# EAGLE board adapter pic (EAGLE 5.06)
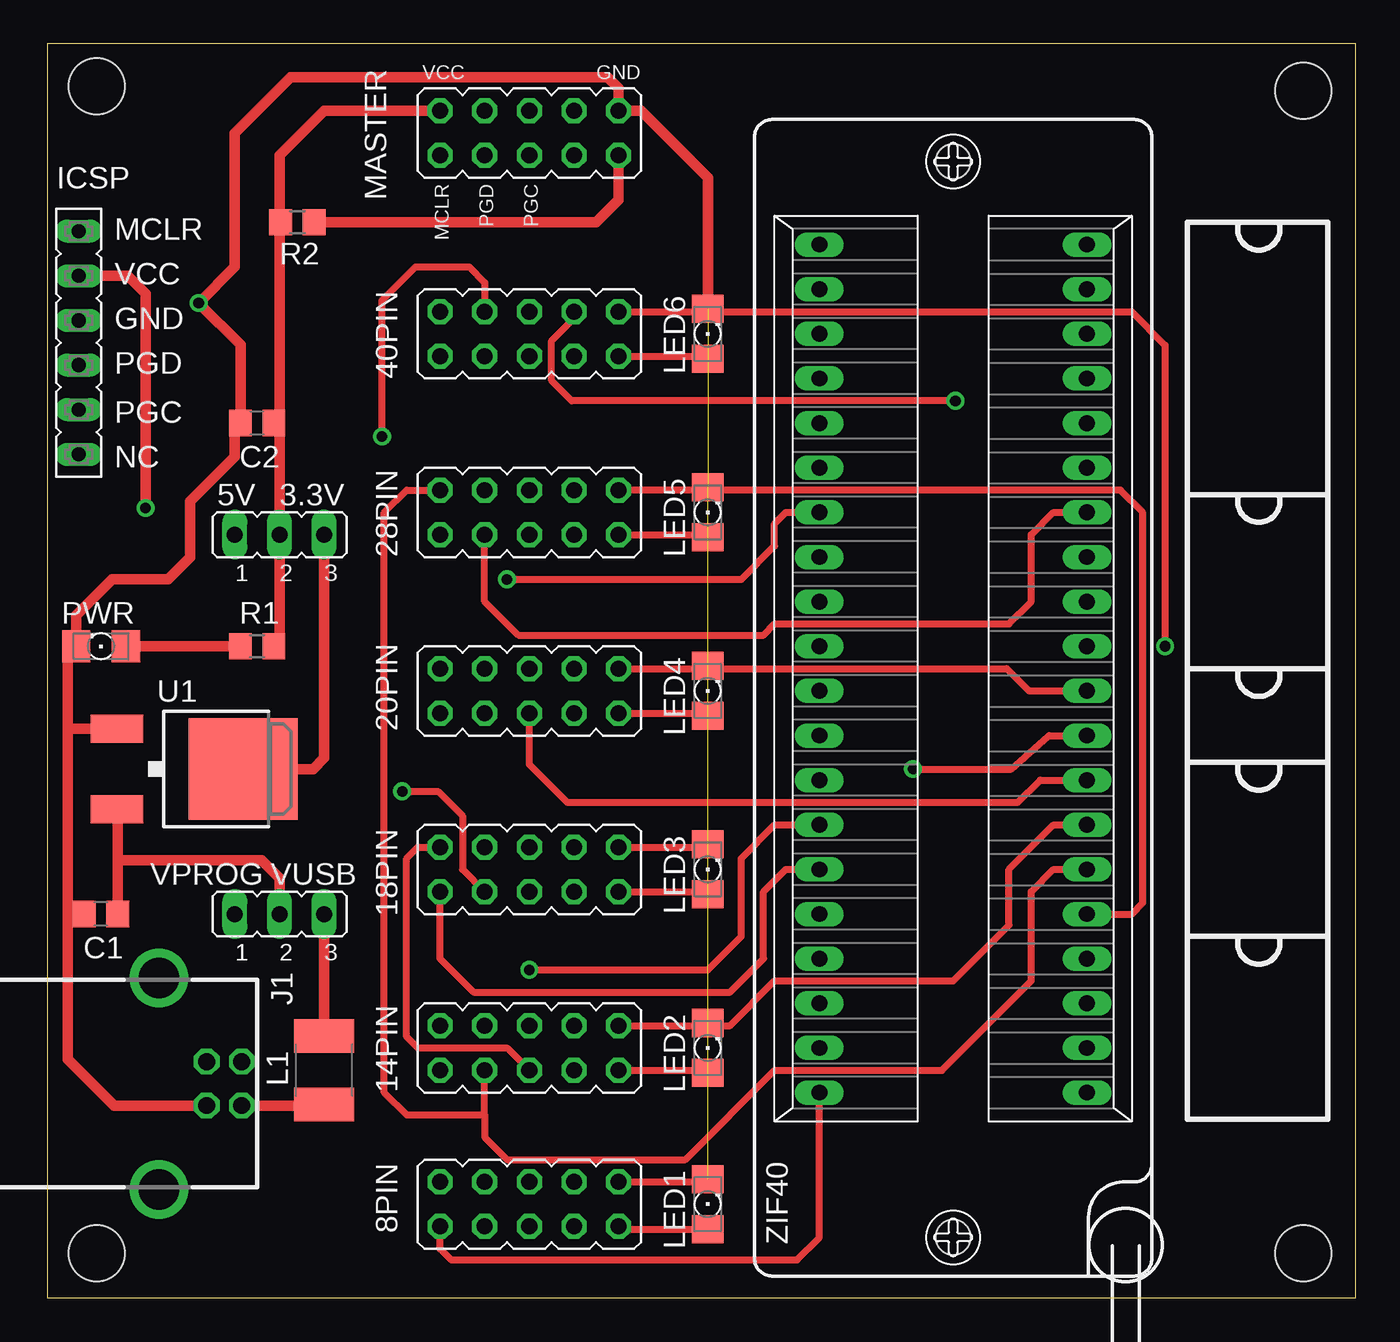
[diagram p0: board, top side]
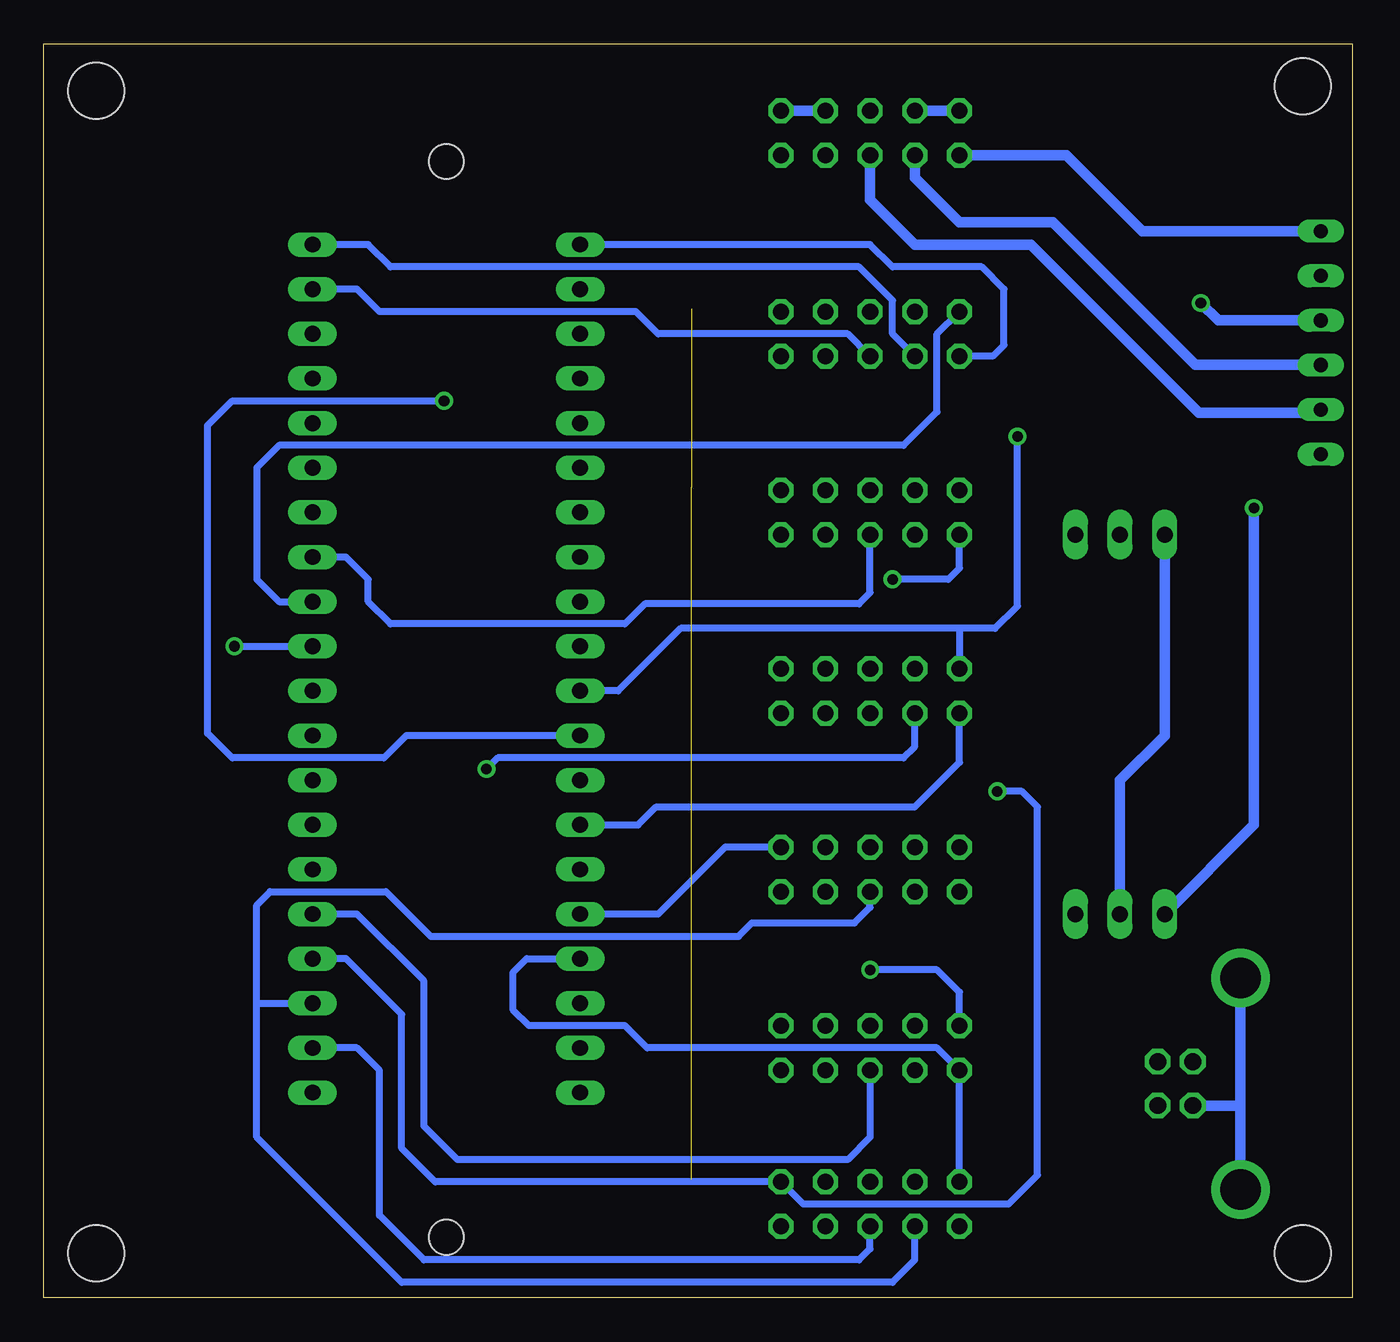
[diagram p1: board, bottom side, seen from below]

Size 74.47 x 71.36 mm. Coordinates in mm from the lower left corner, seen from the top.
Outline: 0,0 74.47,0 74.47,71.36 0,71.36 0,0
Copper layers (1*16): Top 0.035mm / dielectric 1.5mm / Bottom 0.035mm
Design rules "default": minimum track width 10mil, minimum drill 24mil, track to track 8mil, track to pad 8mil, pad to pad 8mil, via to via 8mil, smd to smd 8mil, copper to edge 40mil, drill to drill 8mil, minimum pad ring 10mil, minimum via ring 8mil, stop-mask expansion 4mil, vias tented up to drill 0mil, thermal gap 10mil
Holes 3.2 mm at 2.79,68.96 2.79,2.54 71.5,2.54 71.5,68.71

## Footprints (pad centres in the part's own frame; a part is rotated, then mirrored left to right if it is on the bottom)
JP2 = drill 0.914 long: 1 -2.54,0; 2 0,0; 3 2.54,0
JP5Q = drill 0.914 octagon: 1 -5.08,-1.27; 2 -5.08,1.27; 3 -2.54,-1.27; 4 -2.54,1.27; 5 0,-1.27; 6 0,1.27; 7 2.54,-1.27; 8 2.54,1.27; 9 5.08,-1.27; 10 5.08,1.27
C0805 = smd 1.3 x 1.5: 1 -0.95,0; 2 0.95,0
FE06 = drill 0.813 long: 1 -6.35,0; 2 -3.81,0; 3 -1.27,0; 4 1.27,0; 5 3.81,0; 6 6.35,0
PN61729-S = drill 0.95 octagon: 1 1.25,4.71; 2 -1.25,4.71; 3 -1.25,2.71; 4 1.25,2.71 | drill 2.3 pad 2.9 round: S1 -6.02,0; S2 6.02,0
L1812 = smd 1.9 x 3.4: 1 -1.95,0; 2 1.95,0
1206 = smd 1.6 x 1.803: A -1.422,0; C 1.422,0
R0805 = smd 1.3 x 1.5: 1 -0.95,0; 2 0.95,0
DPACK = smd 1.6 x 3: 1 -2.28,-4.8; 3 2.28,-4.8 | smd 5.8 x 6.2: 4 0,2.38
240-1280-00-0602J = drill 0.9 long: 1 -24.13,-7.62; 2 -21.59,-7.62; 3 -19.05,-7.62; 4 -16.51,-7.62; 5 -13.97,-7.62; 6 -11.43,-7.62; 7 -8.89,-7.62; 8 -6.35,-7.62; 9 -3.81,-7.62; 10 -1.27,-7.62; 11 1.27,-7.62; 12 3.81,-7.62; 13 6.35,-7.62; 14 8.89,-7.62; 15 11.43,-7.62; 16 13.97,-7.62; 17 16.51,-7.62; 18 19.05,-7.62; 19 21.59,-7.62; 20 24.13,-7.62; 21 24.13,7.62; 22 21.59,7.62; 23 19.05,7.62; 24 16.51,7.62; 25 13.97,7.62; 26 11.43,7.62; 27 8.89,7.62; 28 6.35,7.62; 29 3.81,7.62; 30 1.27,7.62; 31 -1.27,7.62; 32 -3.81,7.62; 33 -6.35,7.62; 34 -8.89,7.62; 35 -11.43,7.62; 36 -13.97,7.62; 37 -16.51,7.62; 38 -19.05,7.62; 39 -21.59,7.62; 40 -24.13,7.62 | hole 2: 28.86,0; -32.36,0

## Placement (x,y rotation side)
5V  [JP2]  13.21,43.43 0 top
8PIN  [JP5Q]  27.43,5.33 0 top
14PIN  [JP5Q]  27.43,14.22 0 top
18PIN  [JP5Q]  27.43,24.38 0 top
20PIN  [JP5Q]  27.43,34.54 0 top
28PIN  [JP5Q]  27.43,44.7 0 top
40PIN  [JP5Q]  27.43,54.86 0 top
C1  [C0805]  3.05,21.84 180 top
C2  [C0805]  11.94,49.78 180 top
ICSP  [FE06]  1.78,54.36 270 top
J1  PN61729-S  [PN61729-S]  6.35,12.19 270 top
L1  [L1812]  15.75,12.95 90 top
LED1  [1206]  37.59,5.33 90 top
LED2  [1206]  37.59,14.22 90 top
LED3  [1206]  37.59,24.38 90 top
LED4  [1206]  37.59,34.54 90 top
LED5  [1206]  37.59,44.7 90 top
LED6  [1206]  37.59,54.86 90 top
MASTER  [JP5Q]  27.43,66.29 0 top
PWR  [1206]  3.05,37.08 180 top
R1  [R0805]  11.94,37.08 0 top
R2  [R0805]  14.22,61.21 0 top
U1  LM1117 3V3  [DPACK]  8.76,30.1 270 top
VPROG  [JP2]  13.21,21.84 0 top
ZIF40  [240-1280-00-0602J]  51.56,35.81 90 top

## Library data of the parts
5V 8PIN 14PIN 18PIN 20PIN 28PIN 40PIN MASTER VPROG = jumper
C1 C2 L1 R1 R2 = rcl
ICSP = con-lsta
J1 = con-berg
LED1-LED6 PWR = led
U1 = v-reg
ZIF40 = con-3m

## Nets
GND: C1.2 C2.2 ICSP.3 J1.4 J1.S1 J1.S2 LED1.C LED2.C LED3.C LED4.C LED5.C LED6.C MASTER.8 MASTER.10 PWR.C U1.1
LED_ON: MASTER.9 R2.2
MCLR: ICSP.1 MASTER.1
N$1: 40PIN.1 ZIF40.21
N$2: ZIF40.22
N$3: ZIF40.23
N$4: ZIF40.24
N$5: ZIF40.25
N$6: ZIF40.26
N$7: 28PIN.1 ZIF40.27
N$8: ZIF40.28
N$9: ZIF40.29
N$10: ZIF40.30
N$11: 20PIN.2 40PIN.4 ZIF40.31
N$12: 40PIN.8 ZIF40.32
N$13: ZIF40.33
N$14: 14PIN.2 20PIN.1 ZIF40.34
N$15: 18PIN.1 ZIF40.35
N$16: 18PIN.10 ZIF40.36
N$17: 8PIN.2 14PIN.1 ZIF40.37
N$18: ZIF40.38
N$19: ZIF40.39
N$20: 8PIN.1 ZIF40.40
N$21: ZIF40.1
N$22: 8PIN.5 ZIF40.2
N$23: 8PIN.3 18PIN.5 ZIF40.3
N$24: 8PIN.10 18PIN.3 ZIF40.4
N$25: 14PIN.5 18PIN.2 28PIN.10 ZIF40.5
N$26: 14PIN.3 28PIN.2 ZIF40.6
N$27: 14PIN.10 ZIF40.7
N$28: 20PIN.5 ZIF40.8
N$29: 20PIN.3 ZIF40.9
N$30: 20PIN.10 ZIF40.10
N$31: 40PIN.10 ZIF40.11
N$32: 40PIN.2 ZIF40.12
N$33: 28PIN.5 ZIF40.13
N$34: 28PIN.3 ZIF40.14
N$35: ZIF40.15
N$36: ZIF40.16
N$37: ZIF40.17
N$38: ZIF40.18
N$39: 40PIN.5 ZIF40.19
N$40: 40PIN.3 ZIF40.20
N$41: PWR.A R1.1
N$43: 5V.3 U1.4
N$44: 5V.1 C1.1 U1.3 VPROG.2
N$46: 28PIN.9 LED5.A
N$51: L1.2 VPROG.3
N$52: J1.1 L1.1
N$53: ICSP.2 VPROG.1
N$55: ICSP.6
N$59: 40PIN.9 LED6.A
N$66: 20PIN.9 LED4.A
N$76: 18PIN.9 LED3.A
N$86: 14PIN.9 LED2.A
N$96: 8PIN.9 LED1.A
PGD: ICSP.4 MASTER.3
PGS: ICSP.5 MASTER.5
VDD: 5V.2 C2.1 MASTER.2 MASTER.4 R1.2 R2.1

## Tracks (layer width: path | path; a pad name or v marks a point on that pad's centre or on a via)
GND  (via drill 0.6)  (5 unrouted)
  Top 0.61: LED6.C 37.59,63.75 33.78,67.56 MASTER.10 32.51,68.83 31.88,69.47 13.84,69.47 10.67,66.29 10.67,58.67 v8.61,56.61 10.99,54.23 C2.2 10.67,49.46 10.67,47.88 8.13,45.34 8.13,42.16 6.86,40.89 3.68,40.89 1.63,38.84 PWR.C 1.14,37.08 1.14,32.38 | 1.14,21.53 1.14,13.59 3.79,10.94 J1.4 | 1.14,21.53 C1.2 | 1.14,21.53 1.14,32.38 | 1.14,32.38 U1.1
  Bottom 0.61: MASTER.10 MASTER.8 | ICSP.3 7.62,55.63 v8.61,56.61 | 6.35,10.94 J1.S1 | J1.S2 6.35,10.94 | 6.35,10.94 J1.4
LED_ON
  Top 0.61: MASTER.9 32.51,62.48 31.24,61.21 R2.2
MCLR
  Bottom 0.61: ICSP.1 11.94,60.71 16.26,65.02 MASTER.1
N$1
  Bottom 0.406: ZIF40.21 27.43,59.94 26.16,58.67 21.08,58.67 19.81,57.4 19.81,54.23 20.45,53.59 40PIN.1
N$7  (via drill 0.6)
  Top 0.406: v26.16,40.89 39.5,40.89 41.4,42.8 41.4,44.07 42.04,44.7 ZIF40.27
  Bottom 0.406: 28PIN.1 22.35,41.53 22.99,40.89 v26.16,40.89
N$11  (via drill 0.6)
  Top 0.406: v19.05,49.02 19.05,56.77 20.96,58.67 24,58.67 24.89,57.78 40PIN.4
  Bottom 0.406: v19.05,49.02 19.05,39.37 20.32,38.1 22.35,38.1 | ZIF40.31 41.78,34.54 38.23,38.1 22.35,38.1 | 22.35,38.1 20PIN.2
N$12  (via drill 0.6)
  Top 0.406: 40PIN.8 29.97,55.75 28.7,54.48 28.7,52.2 29.84,51.05 v51.69,51.05
  Bottom 0.406: v51.69,51.05 63.75,51.05 65.15,49.66 65.15,32.13 63.75,30.73 55.12,30.73 53.85,32 ZIF40.32
N$14  (via drill 0.6)
  Top 0.406: v27.43,18.67 37.59,18.67 39.5,20.57 39.5,25.02 41.4,26.92 ZIF40.34
  Bottom 0.406: 14PIN.2 22.35,17.4 23.62,18.67 v27.43,18.67 | 20PIN.1 22.35,30.48 24.89,27.94 39.62,27.94 40.64,26.92 ZIF40.34
N$15
  Top 0.406: 18PIN.1 22.35,19.3 24.26,17.4 38.86,17.4 40.77,19.3 40.77,23.11 42.04,24.38 ZIF40.35
N$16
  Top 0.406: 18PIN.10 37.59,25.65
  Bottom 0.406: 18PIN.10 35.69,25.65 39.5,21.84 ZIF40.36
N$17
  Bottom 0.406: 8PIN.2 14PIN.1 23.62,14.22 40.13,14.22 41.4,15.49 46.86,15.49 47.75,16.38 47.75,18.54 46.99,19.3 ZIF40.37
N$20
  Top 0.406: 8PIN.1 22.35,2.79 22.99,2.16 42.67,2.16 43.94,3.43 ZIF40.40
N$22
  Bottom 0.406: 8PIN.5 27.43,2.79 28.07,2.16 52.83,2.16 55.37,4.7 55.37,12.95 56.64,14.22 ZIF40.2
N$23
  Bottom 0.406: 8PIN.3 24.89,2.16 26.16,0.89 54.1,0.89 62.36,9.14 62.36,16.76 | 62.36,16.76 ZIF40.3 | 18PIN.5 27.43,22.23 28.32,21.34 34.16,21.34 34.92,20.57 52.45,20.57 54.99,23.11 61.59,23.11 62.36,22.35 62.36,16.76
N$24  (via drill 0.6)
  Top 0.406: 8PIN.10 37.59,6.6 | 18PIN.3 23.62,24.38 23.62,27.43 22.22,28.83 v20.19,28.83
  Bottom 0.406: ZIF40.4 57.28,19.3 54.1,16.13 54.1,8.51 52.2,6.6 8PIN.10 31.24,5.33 19.56,5.33 17.91,6.98 17.91,27.94 18.8,28.83 v20.19,28.83
N$25
  Top 0.406: 14PIN.5 26.16,14.22 21.08,14.22 20.45,14.86 20.45,25.02 21.08,25.65 18PIN.2 | 28PIN.10 61.09,45.97 62.36,44.7 62.36,22.48 61.72,21.84 ZIF40.5
  Bottom 0.406: 14PIN.5 27.43,9.14 28.7,7.87 50.93,7.87 52.83,9.78 52.83,18.03 56.64,21.84 ZIF40.5
N$26
  Top 0.406: 24.89,10.41 24.89,9.14 26.16,7.87 36.32,7.87 41.4,12.95 50.93,12.95 56.01,18.03 56.01,23.11 57.28,24.38 ZIF40.6 | 24.89,10.41 14PIN.3 | 24.89,10.41 20.45,10.41 19.18,11.68 19.18,44.7 20.45,45.97 28PIN.2
N$27
  Top 0.406: 14PIN.10 38.86,15.49 41.4,18.03 51.56,18.03 54.74,21.21 54.74,24.38 57.28,26.92 ZIF40.7
N$28
  Top 0.406: ZIF40.8 56.52,29.46 55.24,28.19 29.59,28.19 27.43,30.35 20PIN.5
N$29  (via drill 0.6)
  Top 0.406: v49.28,30.1 54.86,30.1 57.02,32 ZIF40.9
  Bottom 0.406: 20PIN.3 24.89,31.37 25.53,30.73 48.64,30.73 v49.28,30.1
N$30
  Top 0.406: 20PIN.10 54.61,35.81 55.88,34.54 ZIF40.10
N$31  (via drill 0.6)
  Top 0.406: 40PIN.10 61.72,56.13 63.63,54.23 v63.63,37.08
  Bottom 0.406: v63.63,37.08 ZIF40.11
N$32
  Bottom 0.406: 40PIN.2 23.62,54.86 23.62,50.42 25.53,48.51 61.09,48.51 62.36,47.24 62.36,40.89 61.09,39.62 ZIF40.12
N$33
  Bottom 0.406: 28PIN.5 27.43,40.13 28.07,39.5 40.26,39.5 41.4,38.35 54.74,38.35 56.01,39.62 56.01,40.89 57.28,42.16 ZIF40.13
N$34
  Top 0.406: 28PIN.3 24.89,39.62 26.8,37.72 40.77,37.72 41.4,38.35 54.74,38.35 56.01,39.62 56.01,43.43 57.28,44.7 ZIF40.14
N$39
  Bottom 0.406: 40PIN.5 28.7,54.86 39.5,54.86 40.77,56.13 55.37,56.13 56.64,57.4 ZIF40.19
N$40
  Bottom 0.406: 40PIN.3 26.16,54.86 26.16,56.77 28.07,58.67 54.74,58.67 56.01,59.94 ZIF40.20
N$41
  Top 0.61: PWR.A R1.1
N$43
  Top 0.61: 5V.3 15.75,30.73 15.11,30.1 U1.4
N$44
  Top 0.61: U1.3 4,27.82 4,24.96 | C1.1 4,24.96 | 4,24.96 4.06,24.89 12.19,24.89 13.21,23.88 VPROG.2
  Bottom 0.61: VPROG.2 13.21,29.46 10.67,32 5V.1
N$46
  Top 0.406: 28PIN.9 37.44,43.43 LED5.A
N$51
  Top 0.61: L1.2 VPROG.3
N$52
  Top 0.61: 15.18,10.43 L1.1 15.69,10.94 J1.1
N$53  (via drill 0.6)
  Top 0.61: ICSP.2 4.57,58.17 5.59,57.15 v5.59,44.96
  Bottom 0.61: v5.59,44.96 5.59,26.92 VPROG.1
N$59
  Top 0.406: 40PIN.9 37.44,53.59 LED6.A
N$66
  Top 0.406: 20PIN.9 37.44,33.27 LED4.A
N$76
  Top 0.406: 18PIN.9 37.44,23.11 LED3.A
N$86
  Top 0.406: 14PIN.9 37.44,12.95 LED2.A
N$96
  Top 0.406: LED1.A 32.66,3.91 8PIN.9
PGD
  Bottom 0.61: MASTER.3 24.89,63.75 22.35,61.21 17.02,61.21 8.92,53.11 1.3,53.11 ICSP.4
PGS
  Bottom 0.61: MASTER.5 27.43,62.48 24.89,59.94 18.29,59.94 8.72,50.38 1.44,50.38 ICSP.5
VDD
  Top 0.61: MASTER.2 15.75,67.56 13.21,65.02 13.21,61.21 | 13.21,61.21 13.21,50.1 C2.1 13.21,49.46 5V.2 13.21,37.4 R1.2 | 13.21,61.21 R2.1
  Bottom 0.61: MASTER.2 MASTER.4

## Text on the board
tNames: VCC | GND | PGD | PGC | MCLR | MCLR | VCC | GND | PGD | PGC | NC | 3.3V | VUSB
